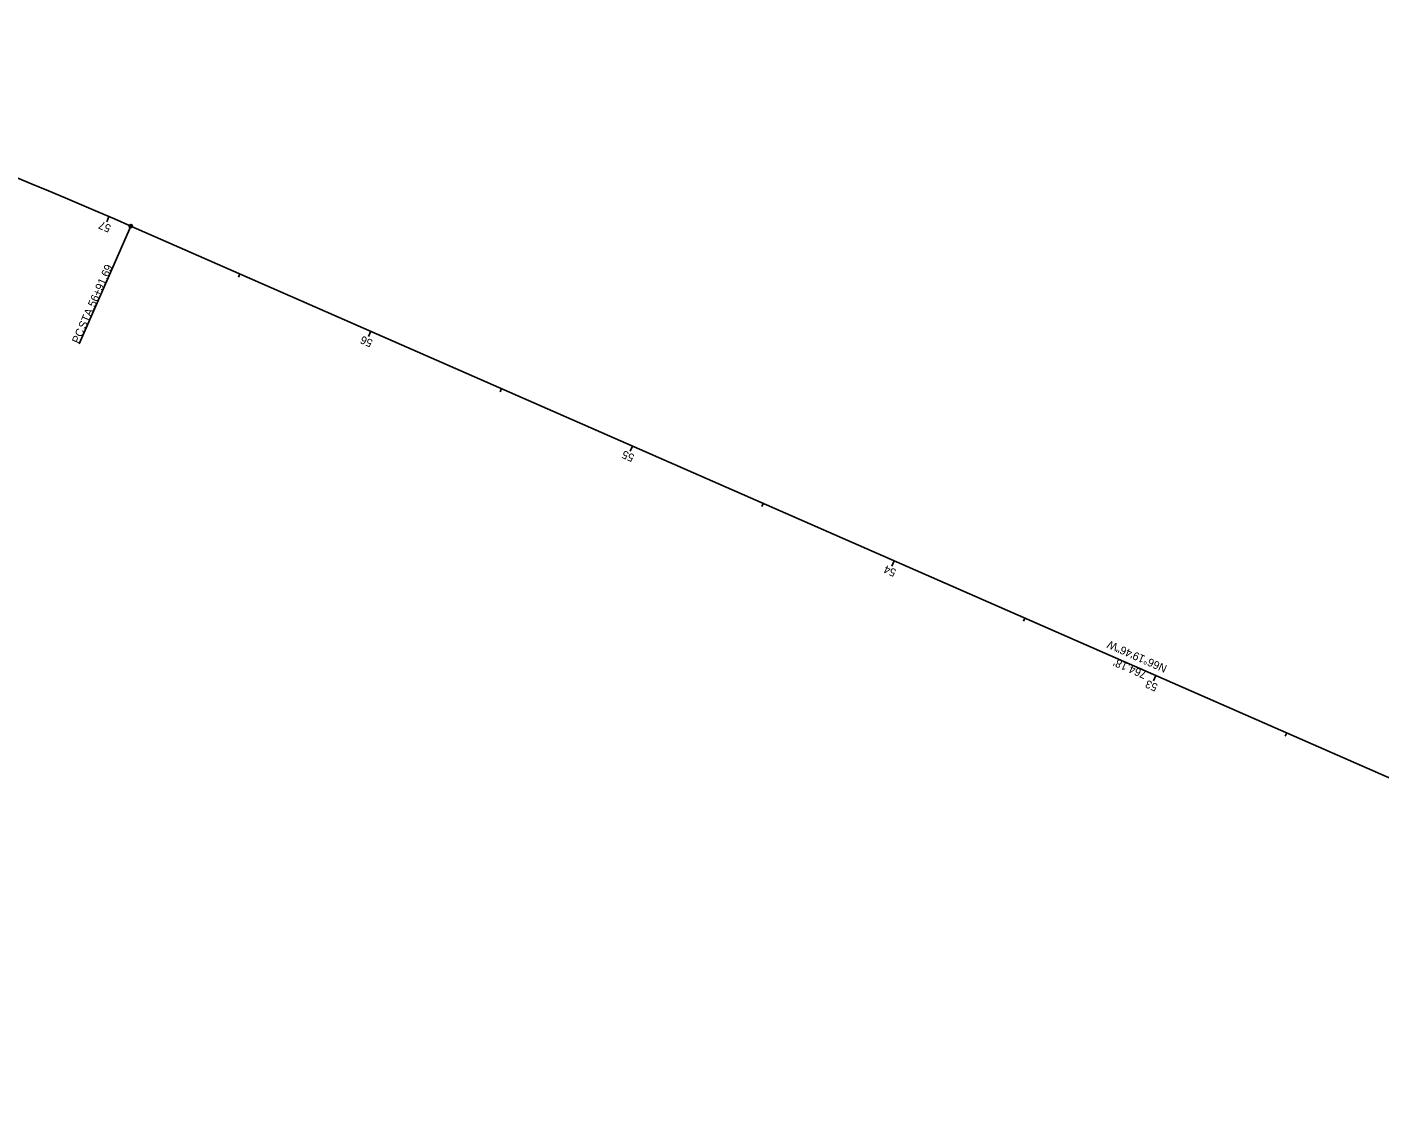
# Model space of a CAD drawing. Extents: x 1698884 to 1700452, y 716861 to 717517.
# Drawn here: x 1699503.7 to 1699977.1, y 717001.1 to 717377.5 of the extents above; entities that cross this region are included whole.
import ezdxf

# ---------------------------------------------------------------- set-up
doc = ezdxf.new("R2010")
doc.units = 0
for name, color, linetype in [('PF_X_Ground_Line', 7, 'Continuous'), ('RS_Raster1', 7, 'Continuous'), ('RW_X_CL_100_Bearings', 7, 'Continuous'), ('RW_X_CL_100_Cardinal_Points', 7, 'Continuous'), ('RW_X_CL_100_Curve_Data', 7, 'Continuous'), ('RW_X_CL_100_Distances', 7, 'Continuous')]:
    doc.layers.add(name, color=color, linetype=linetype)

msp = doc.modelspace()

# ---------------------------------------------------------------- linework, layer by layer
at = {"layer": 'RS_Raster1'}
msp.add_line((1700239.87, 717001.09), (1699539.98, 717307.89), dxfattribs=at)
at = {"layer": 'RW_X_CL_100_Bearings'}
msp.add_line((1700239.87, 717001.09), (1699539.98, 717307.89), dxfattribs=at)
msp.add_arc((1698839.5, 715709.93), 1744.75, 66.32957, 72.89737, dxfattribs=at)
at = {"layer": 'RW_X_CL_100_Curve_Data'}
msp.add_line((1699539.98, 717307.89), (1699521.91, 717266.68), dxfattribs=at)
msp.add_circle((1699539.98, 717307.89), 0.6, dxfattribs=at)
at = {"layer": 'RW_X_CL_100_Distances'}
for p, q in [((1699532.36, 717311.21), (1699531.56, 717309.38)), ((1699578.16, 717291.16), (1699577.68, 717290.06)), ((1699623.95, 717271.08), (1699623.15, 717269.25)), ((1699669.75, 717251.01), (1699669.26, 717249.91)), ((1699715.54, 717230.93), (1699714.74, 717229.1)), ((1699761.33, 717210.86), (1699760.85, 717209.76)), ((1699807.13, 717190.79), (1699806.32, 717188.95)), ((1699852.92, 717170.71), (1699852.44, 717169.61)), ((1699898.71, 717150.64), (1699897.91, 717148.81)), ((1699944.51, 717130.57), (1699944.03, 717129.47))]:
    msp.add_line(p, q, dxfattribs=at)

# ---------------------------------------------------------------- texts
at = {"layer": 'PF_X_Ground_Line'}
msp.add_text("764.18'", height=2.8, rotation=156.3296, dxfattribs=at).set_placement((1699895.8, 717151.87))
at = {"layer": 'RW_X_CL_100_Cardinal_Points'}
msp.add_text('N66°19\'46"W', height=2.8, rotation=156.3296, dxfattribs=at).set_placement((1699902.87, 717154.06))
at = {"layer": 'RW_X_CL_100_Curve_Data'}
for s, p in [('56+91.69', (1699527.4, 717279.28)), (' STA. ', (1699523.65, 717270.74)), ('PC', (1699521.81, 717266.53))]:
    msp.add_text(s, height=2.8, rotation=66.3296, dxfattribs=at).set_placement(p)
at = {"layer": 'RW_X_CL_100_Distances'}
for s, rotation, p in [('57', 156.6025, (1699533.32, 717308.07)), ('56', 156.3296, (1699624.91, 717267.93)), ('55', 156.3296, (1699716.45, 717227.81)), ('54', 156.3296, (1699808.1, 717187.63)), ('53', 156.3296, (1699899.62, 717147.51))]:
    msp.add_text(s, height=2.8, rotation=rotation, dxfattribs=at).set_placement(p)

doc.saveas('drawing.dxf')
